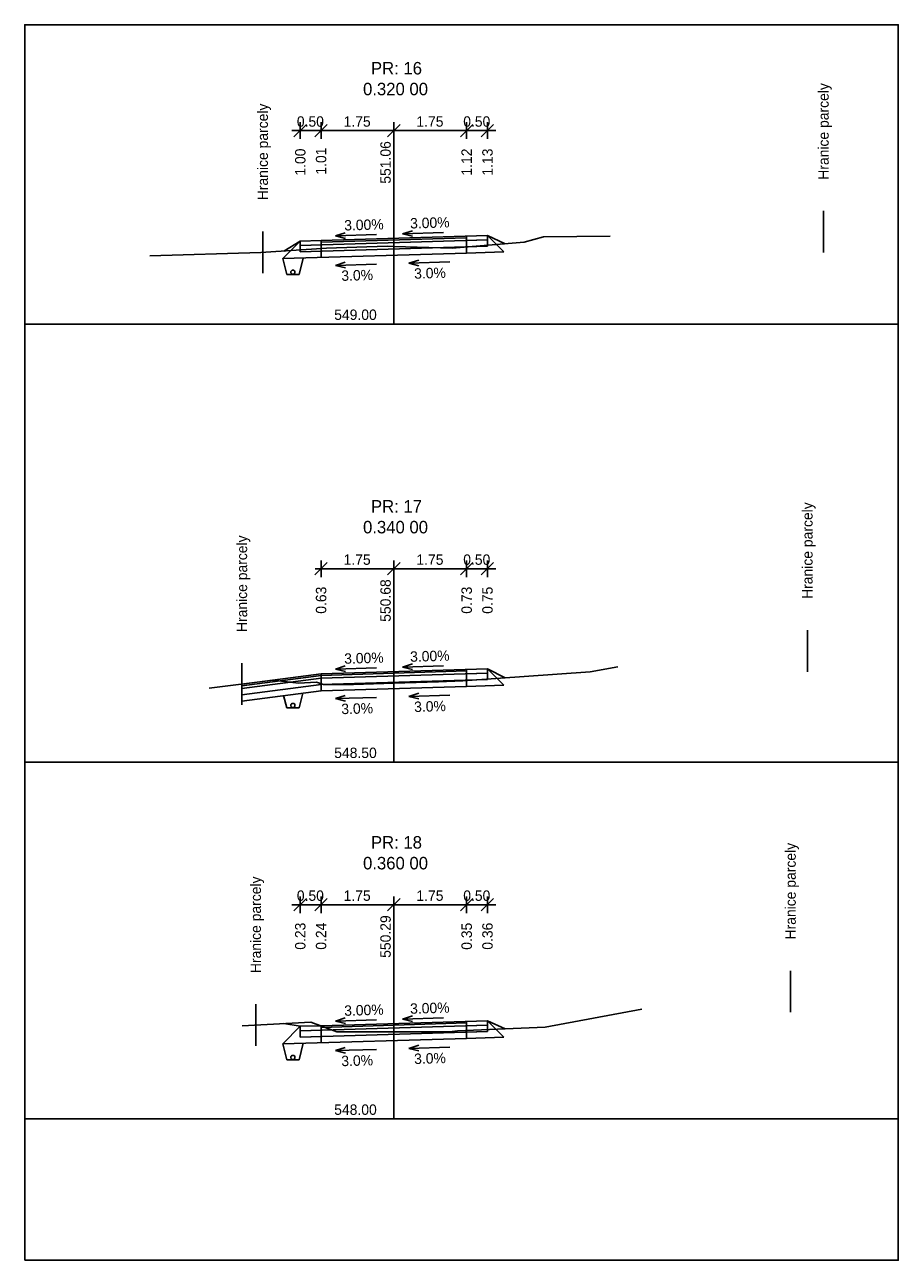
# Model space of a CAD drawing. Extents: x -603737 to -603383, y -1112154 to -1112124.
# Drawn here: x -603584.08 to -603563.08, y -1112153.84 to -1112124.14 of the extents above; entities that cross this region are included whole.
import ezdxf

# ---------------------------------------------------------------- set-up
doc = ezdxf.new("R2010")
doc.units = 0
for name, color, linetype in [('_křivky z hran', 7, 'Continuous'), ('_netisk', 7, 'Continuous'), ('C3D_Podsestava-Popis', 7, 'Continuous'), ('C3D_PP-Popisek', 7, 'Continuous'), ('C3D_PR', 7, 'Continuous'), ('C3D_ZPR', 7, 'Continuous'), ('Default', 7, 'Continuous'), ('konstrukce', 7, 'Continuous')]:
    doc.layers.add(name, color=color, linetype=linetype)

# ---------------------------------------------------------------- blocks, each defined once
blk = doc.blocks.new('_Oblique')
at = {"layer": 'Default'}
blk.add_line((-0.5, -0.5), (0.5, 0.5), dxfattribs=at)
blk = doc.blocks.new('AeccTickLine')
at = {"layer": 'Default'}
blk.add_line((0, 1), (0, -1), dxfattribs=at)

msp = doc.modelspace()

# ---------------------------------------------------------------- linework, layer by layer
at = {"layer": '_netisk'}
msp.add_lwpolyline([(-603584.084, -1112153.84), (-603563.084, -1112153.84), (-603563.084, -1112124.14), (-603584.084, -1112124.14)], close=True, dxfattribs=at)
at = {"layer": 'C3D_Podsestava-Popis'}
for p, q in [((-603577.661, -1112126.686), (-603575.211, -1112126.686)), ((-603575.211, -1112126.686), (-603572.761, -1112126.686)), ((-603575.211, -1112127.272), (-603575.211, -1112126.836)), ((-603577.105, -1112137.217), (-603575.211, -1112137.217)), ((-603575.211, -1112137.217), (-603572.761, -1112137.217)), ((-603575.211, -1112137.687), (-603575.211, -1112137.367)), ((-603577.661, -1112145.294), (-603575.211, -1112145.294)), ((-603575.211, -1112145.294), (-603572.761, -1112145.294)), ((-603575.211, -1112146.149), (-603575.211, -1112145.444))]:
    msp.add_line(p, q, dxfattribs=at)
at = {"layer": 'C3D_PP-Popisek'}
for p, q in [((-603576.614, -1112129.214), (-603576.377, -1112129.139)), ((-603575.63, -1112129.185), (-603576.614, -1112129.214)), ((-603576.614, -1112129.214), (-603576.373, -1112129.276)), ((-603575.002, -1112129.166), (-603574.766, -1112129.091)), ((-603574.019, -1112129.136), (-603575.002, -1112129.166)), ((-603575.002, -1112129.166), (-603574.762, -1112129.227)), ((-603576.614, -1112129.925), (-603576.377, -1112129.849)), ((-603574.849, -1112129.872), (-603574.612, -1112129.796)), ((-603573.865, -1112129.842), (-603574.849, -1112129.872)), ((-603575.63, -1112129.895), (-603576.614, -1112129.925)), ((-603576.614, -1112129.925), (-603576.373, -1112129.986)), ((-603574.849, -1112129.872), (-603574.608, -1112129.933)), ((-603576.614, -1112139.629), (-603576.377, -1112139.554)), ((-603575.63, -1112139.6), (-603576.614, -1112139.629)), ((-603576.614, -1112139.629), (-603576.373, -1112139.69)), ((-603575.002, -1112139.581), (-603574.766, -1112139.506)), ((-603574.019, -1112139.551), (-603575.002, -1112139.581)), ((-603575.002, -1112139.581), (-603574.762, -1112139.642)), ((-603574.849, -1112140.287), (-603574.612, -1112140.211)), ((-603573.865, -1112140.257), (-603574.849, -1112140.287)), ((-603576.614, -1112140.34), (-603576.377, -1112140.264)), ((-603575.63, -1112140.31), (-603576.614, -1112140.34)), ((-603576.614, -1112140.34), (-603576.373, -1112140.401)), ((-603574.849, -1112140.287), (-603574.608, -1112140.348)), ((-603575.002, -1112148.042), (-603574.766, -1112147.967)), ((-603576.614, -1112148.091), (-603576.377, -1112148.015)), ((-603575.63, -1112148.061), (-603576.614, -1112148.091)), ((-603576.614, -1112148.091), (-603576.373, -1112148.152)), ((-603574.019, -1112148.013), (-603575.002, -1112148.042)), ((-603575.002, -1112148.042), (-603574.762, -1112148.103)), ((-603576.614, -1112148.801), (-603576.377, -1112148.726)), ((-603575.63, -1112148.771), (-603576.614, -1112148.801)), ((-603576.614, -1112148.801), (-603576.373, -1112148.862)), ((-603574.849, -1112148.748), (-603574.612, -1112148.673)), ((-603573.865, -1112148.718), (-603574.849, -1112148.748)), ((-603574.849, -1112148.748), (-603574.608, -1112148.809))]:
    msp.add_line(p, q, dxfattribs=at)
at = {"layer": 'C3D_PR'}
for points in [[(-603581.074, -1112129.696), (-603578.408, -1112129.618), (-603576.827, -1112129.515), (-603575.375, -1112129.465), (-603575.211, -1112129.47), (-603573.81, -1112129.508), (-603572.076, -1112129.37), (-603571.614, -1112129.239), (-603570.01, -1112129.226)], [(-603579.649, -1112140.091), (-603578.112, -1112139.892), (-603577.501, -1112139.965), (-603577.067, -1112139.941), (-603576.902, -1112140.002), (-603576.181, -1112140.003), (-603575.211, -1112139.969), (-603574.134, -1112139.932), (-603573.55, -1112139.911), (-603570.493, -1112139.697), (-603569.825, -1112139.572)], [(-603578.859, -1112148.204), (-603578.856, -1112148.205), (-603577.203, -1112148.116), (-603576.579, -1112148.345), (-603576.574, -1112148.345), (-603575.211, -1112148.348), (-603573.871, -1112148.352), (-603573.679, -1112148.324), (-603571.575, -1112148.239), (-603569.248, -1112147.801)]]:
    msp.add_lwpolyline(points, dxfattribs=at)
at = {"layer": 'C3D_ZPR'}
for p, q in [((-603575.211, -1112131.336), (-603575.211, -1112126.836)), ((-603564.882, -1112129.617), (-603564.882, -1112128.617)), ((-603578.363, -1112130.109), (-603578.363, -1112129.109)), ((-603576.961, -1112129.325), (-603572.961, -1112129.205)), ((-603576.961, -1112129.365), (-603573.461, -1112129.26)), ((-603573.461, -1112129.26), (-603573.461, -1112129.22)), ((-603573.461, -1112129.63), (-603573.461, -1112129.22)), ((-603572.961, -1112129.465), (-603572.961, -1112129.205)), ((-603572.961, -1112129.465), (-603572.961, -1112129.205)), ((-603572.961, -1112129.205), (-603572.563, -1112129.603)), ((-603572.961, -1112129.205), (-603572.536, -1112129.407)), ((-603572.961, -1112129.205), (-603572.536, -1112129.407)), ((-603577.883, -1112129.763), (-603577.461, -1112129.34)), ((-603577.461, -1112129.34), (-603577.856, -1112129.582)), ((-603577.856, -1112129.582), (-603577.461, -1112129.34)), ((-603577.461, -1112129.45), (-603572.961, -1112129.315)), ((-603577.461, -1112129.34), (-603576.961, -1112129.325)), ((-603577.461, -1112129.6), (-603577.461, -1112129.34)), ((-603577.461, -1112129.6), (-603577.461, -1112129.34)), ((-603577.461, -1112129.45), (-603576.961, -1112129.435)), ((-603577.461, -1112129.6), (-603572.961, -1112129.465)), ((-603576.961, -1112129.735), (-603576.961, -1112129.325)), ((-603576.961, -1112129.435), (-603576.961, -1112129.365)), ((-603573.461, -1112129.33), (-603572.961, -1112129.315)), ((-603573.461, -1112129.48), (-603573.461, -1112129.33)), ((-603573.461, -1112129.48), (-603572.961, -1112129.465)), ((-603577.883, -1112129.763), (-603573.461, -1112129.63)), ((-603577.461, -1112129.6), (-603576.961, -1112129.585)), ((-603576.961, -1112129.735), (-603576.961, -1112129.585)), ((-603573.461, -1112129.63), (-603572.563, -1112129.603)), ((-603584.084, -1112131.336), (-603563.084, -1112131.336)), ((-603575.211, -1112141.867), (-603575.211, -1112137.367)), ((-603565.27, -1112139.693), (-603565.27, -1112138.693)), ((-603578.862, -1112140.489), (-603578.862, -1112139.489)), ((-603576.961, -1112139.74), (-603572.961, -1112139.62)), ((-603573.461, -1112139.675), (-603573.461, -1112139.635)), ((-603573.461, -1112140.045), (-603573.461, -1112139.635)), ((-603572.961, -1112139.88), (-603572.961, -1112139.62)), ((-603572.961, -1112139.88), (-603572.961, -1112139.62)), ((-603572.961, -1112139.62), (-603572.563, -1112140.018)), ((-603572.961, -1112139.62), (-603572.536, -1112139.84)), ((-603572.961, -1112139.62), (-603572.536, -1112139.84)), ((-603576.961, -1112139.78), (-603573.461, -1112139.675)), ((-603576.961, -1112139.85), (-603572.961, -1112139.73)), ((-603576.961, -1112140.15), (-603576.961, -1112139.74)), ((-603576.961, -1112139.85), (-603576.961, -1112139.78)), ((-603576.961, -1112140), (-603572.961, -1112139.88)), ((-603573.461, -1112139.745), (-603572.961, -1112139.73)), ((-603573.461, -1112139.895), (-603573.461, -1112139.745)), ((-603573.461, -1112139.895), (-603572.961, -1112139.88)), ((-603576.961, -1112140.15), (-603576.961, -1112140)), ((-603576.961, -1112140.15), (-603573.461, -1112140.045)), ((-603573.461, -1112140.045), (-603572.563, -1112140.018)), ((-603584.084, -1112141.867), (-603563.084, -1112141.867)), ((-603575.211, -1112150.444), (-603575.211, -1112145.444)), ((-603565.674, -1112147.879), (-603565.674, -1112146.879)), ((-603578.531, -1112148.687), (-603578.531, -1112147.687)), ((-603577.883, -1112148.639), (-603577.461, -1112148.216)), ((-603577.461, -1112148.216), (-603577.856, -1112148.151)), ((-603577.856, -1112148.151), (-603577.461, -1112148.216)), ((-603577.461, -1112148.326), (-603572.961, -1112148.191)), ((-603577.461, -1112148.216), (-603576.961, -1112148.201)), ((-603577.461, -1112148.476), (-603577.461, -1112148.216)), ((-603577.461, -1112148.476), (-603577.461, -1112148.216)), ((-603576.961, -1112148.201), (-603572.961, -1112148.081)), ((-603576.961, -1112148.241), (-603573.461, -1112148.136)), ((-603576.961, -1112148.611), (-603576.961, -1112148.201)), ((-603576.961, -1112148.311), (-603576.961, -1112148.241)), ((-603573.461, -1112148.136), (-603573.461, -1112148.096)), ((-603573.461, -1112148.506), (-603573.461, -1112148.096)), ((-603573.461, -1112148.206), (-603572.961, -1112148.191)), ((-603573.461, -1112148.356), (-603573.461, -1112148.206)), ((-603572.961, -1112148.341), (-603572.961, -1112148.081)), ((-603572.961, -1112148.341), (-603572.961, -1112148.081)), ((-603572.961, -1112148.081), (-603572.563, -1112148.479)), ((-603572.961, -1112148.081), (-603572.536, -1112148.277)), ((-603572.961, -1112148.081), (-603572.536, -1112148.277)), ((-603577.883, -1112148.639), (-603573.461, -1112148.506)), ((-603577.461, -1112148.326), (-603576.961, -1112148.311)), ((-603577.461, -1112148.476), (-603572.961, -1112148.341)), ((-603577.461, -1112148.476), (-603576.961, -1112148.461)), ((-603576.961, -1112148.611), (-603576.961, -1112148.461)), ((-603573.461, -1112148.356), (-603572.961, -1112148.341)), ((-603573.461, -1112148.506), (-603572.563, -1112148.479)), ((-603584.084, -1112150.444), (-603563.084, -1112150.444))]:
    msp.add_line(p, q, dxfattribs=at)
for points in [[(-603578.862, -1112139.989), (-603576.961, -1112139.74)], [(-603578.862, -1112140.029), (-603576.961, -1112139.78)], [(-603578.862, -1112140.099), (-603576.961, -1112139.85)], [(-603578.862, -1112140.249), (-603576.961, -1112140)], [(-603578.862, -1112140.399), (-603576.961, -1112140.15)]]:
    msp.add_lwpolyline(points, dxfattribs=at)
at = {"layer": 'konstrukce'}
for p, q in [((-603577.787, -1112130.148), (-603577.883, -1112129.763)), ((-603577.487, -1112130.148), (-603577.387, -1112129.748)), ((-603577.487, -1112130.148), (-603577.787, -1112130.148)), ((-603577.487, -1112140.563), (-603577.398, -1112140.207)), ((-603577.787, -1112140.563), (-603577.861, -1112140.268)), ((-603577.487, -1112140.563), (-603577.787, -1112140.563)), ((-603577.787, -1112149.024), (-603577.883, -1112148.639)), ((-603577.487, -1112149.024), (-603577.387, -1112148.624)), ((-603577.487, -1112149.024), (-603577.787, -1112149.024))]:
    msp.add_line(p, q, dxfattribs=at)
for centre in [(-603577.637, -1112130.088), (-603577.637, -1112140.503), (-603577.637, -1112148.964)]:
    msp.add_circle(centre, 0.05, dxfattribs=at)

# ---------------------------------------------------------------- block references
at = {"layer": '_křivky z hran', "rotation": 180}
for name, p, xscale, yscale in [('_Oblique', (-603577.461, -1112126.686), 0.3, 0.3), ('AeccTickLine', (-603577.461, -1112126.686), 0.2, 0.20000000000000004), ('_Oblique', (-603576.961, -1112126.686), 0.3, 0.3), ('AeccTickLine', (-603576.961, -1112126.686), 0.2, 0.20000000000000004), ('_Oblique', (-603575.211, -1112126.686), 0.3, 0.3), ('AeccTickLine', (-603575.211, -1112126.686), 0.2, 0.20000000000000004), ('_Oblique', (-603576.961, -1112137.217), 0.3, 0.3), ('AeccTickLine', (-603576.961, -1112137.217), 0.2, 0.20000000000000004), ('_Oblique', (-603575.211, -1112137.217), 0.3, 0.3), ('AeccTickLine', (-603575.211, -1112137.217), 0.2, 0.20000000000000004), ('_Oblique', (-603577.461, -1112145.294), 0.3, 0.3), ('AeccTickLine', (-603577.461, -1112145.294), 0.2, 0.20000000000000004), ('_Oblique', (-603576.961, -1112145.294), 0.3, 0.3), ('AeccTickLine', (-603576.961, -1112145.294), 0.2, 0.20000000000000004), ('_Oblique', (-603575.211, -1112145.294), 0.3, 0.3), ('AeccTickLine', (-603575.211, -1112145.294), 0.2, 0.20000000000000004)]:
    msp.add_blockref(name, p, dxfattribs=dict(at, xscale=xscale, yscale=yscale))
at = {"layer": '_křivky z hran'}
for name, p, xscale, yscale in [('_Oblique', (-603575.211, -1112126.686), 0.3, 0.3), ('AeccTickLine', (-603575.211, -1112126.686), 0.2, 0.20000000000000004), ('_Oblique', (-603573.461, -1112126.686), 0.3, 0.3), ('AeccTickLine', (-603573.461, -1112126.686), 0.2, 0.20000000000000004), ('_Oblique', (-603572.961, -1112126.686), 0.3, 0.3), ('AeccTickLine', (-603572.961, -1112126.686), 0.2, 0.20000000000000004), ('_Oblique', (-603575.211, -1112137.217), 0.3, 0.3), ('AeccTickLine', (-603575.211, -1112137.217), 0.2, 0.20000000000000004), ('_Oblique', (-603573.461, -1112137.217), 0.3, 0.3), ('AeccTickLine', (-603573.461, -1112137.217), 0.2, 0.20000000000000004), ('_Oblique', (-603572.961, -1112137.217), 0.3, 0.3), ('AeccTickLine', (-603572.961, -1112137.217), 0.2, 0.20000000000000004), ('_Oblique', (-603575.211, -1112145.294), 0.3, 0.3), ('AeccTickLine', (-603575.211, -1112145.294), 0.2, 0.20000000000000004), ('_Oblique', (-603573.461, -1112145.294), 0.3, 0.3), ('AeccTickLine', (-603573.461, -1112145.294), 0.2, 0.20000000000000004), ('_Oblique', (-603572.961, -1112145.294), 0.3, 0.3), ('AeccTickLine', (-603572.961, -1112145.294), 0.2, 0.20000000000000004)]:
    msp.add_blockref(name, p, dxfattribs=dict(at, xscale=xscale, yscale=yscale))

# ---------------------------------------------------------------- texts
at = {"layer": 'C3D_Podsestava-Popis'}
for s, rotation, p in [('0.50', 360, (-603577.542, -1112126.592)), ('1.75', 360, (-603576.418, -1112126.592)), ('1.75', 360, (-603576.418, -1112126.592)), ('1.75', 360, (-603574.668, -1112126.592)), ('1.75', 360, (-603574.668, -1112126.592)), ('0.50', 360, (-603573.542, -1112126.592)), ('1.00', 90, (-603577.335, -1112127.768)), ('1.00', 90, (-603577.335, -1112127.768)), ('1.01', 90, (-603576.835, -1112127.744)), ('551.06', 90, (-603575.285, -1112127.962)), ('1.12', 90, (-603573.335, -1112127.767)), ('1.13', 90, (-603572.835, -1112127.768)), ('1.13', 90, (-603572.835, -1112127.768)), ('3.00%', 1.7184, (-603576.4, -1112129.088)), ('3.00%', 1.7184, (-603574.816, -1112129.04)), ('3.0%', 1.7184, (-603576.469, -1112130.299)), ('3.0%', 1.7184, (-603574.719, -1112130.247)), ('1.75', 360, (-603576.418, -1112137.123)), ('1.75', 360, (-603576.418, -1112137.123)), ('1.75', 360, (-603574.668, -1112137.123)), ('1.75', 360, (-603574.668, -1112137.123)), ('0.50', 360, (-603573.542, -1112137.123)), ('550.68', 90, (-603575.285, -1112138.493)), ('0.63', 90, (-603576.835, -1112138.299)), ('0.73', 90, (-603573.335, -1112138.299)), ('0.75', 90, (-603572.835, -1112138.3)), ('0.75', 90, (-603572.835, -1112138.3)), ('3.00%', 1.7184, (-603576.4, -1112139.503)), ('3.00%', 1.7184, (-603574.816, -1112139.455)), ('3.0%', 1.7184, (-603576.469, -1112140.714)), ('3.0%', 1.7184, (-603574.719, -1112140.662)), ('0.50', 360, (-603577.542, -1112145.2)), ('1.75', 360, (-603576.418, -1112145.2)), ('1.75', 360, (-603576.418, -1112145.2)), ('1.75', 360, (-603574.668, -1112145.2)), ('1.75', 360, (-603574.668, -1112145.2)), ('0.50', 360, (-603573.542, -1112145.2)), ('550.29', 90, (-603575.285, -1112146.57)), ('0.23', 90, (-603577.335, -1112146.375)), ('0.23', 90, (-603577.335, -1112146.375)), ('0.24', 90, (-603576.835, -1112146.375)), ('0.35', 90, (-603573.335, -1112146.376)), ('0.36', 90, (-603572.835, -1112146.375)), ('0.36', 90, (-603572.835, -1112146.375)), ('3.00%', 1.7184, (-603574.816, -1112147.916)), ('3.00%', 1.7184, (-603576.4, -1112147.965)), ('3.0%', 1.7184, (-603574.719, -1112149.123)), ('3.0%', 1.7184, (-603576.469, -1112149.176))]:
    msp.add_text(s, height=0.25, rotation=rotation, dxfattribs=at).set_placement(p)
at = {"layer": 'C3D_ZPR'}
for s, p in [('PR: 16', (-603575.761, -1112125.336)), ('0.320 00', (-603575.951, -1112125.836)), ('PR: 17', (-603575.761, -1112135.867)), ('0.340 00', (-603575.951, -1112136.367)), ('PR: 18', (-603575.761, -1112143.944)), ('0.360 00', (-603575.951, -1112144.444))]:
    msp.add_text(s, height=0.3, dxfattribs=at).set_placement(p)
for s, rotation, p in [('Hranice parcely', 90, (-603564.757, -1112127.867)), ('Hranice parcely', 90, (-603578.238, -1112128.359)), ('549.00', 360, (-603576.644, -1112131.236)), ('Hranice parcely', 90, (-603565.145, -1112137.943)), ('Hranice parcely', 90, (-603578.737, -1112138.739)), ('548.50', 360, (-603576.644, -1112141.767)), ('Hranice parcely', 90, (-603565.549, -1112146.129)), ('Hranice parcely', 90, (-603578.406, -1112146.937)), ('548.00', 360, (-603576.644, -1112150.344))]:
    msp.add_text(s, height=0.25, rotation=rotation, dxfattribs=at).set_placement(p)

doc.saveas('drawing.dxf')
